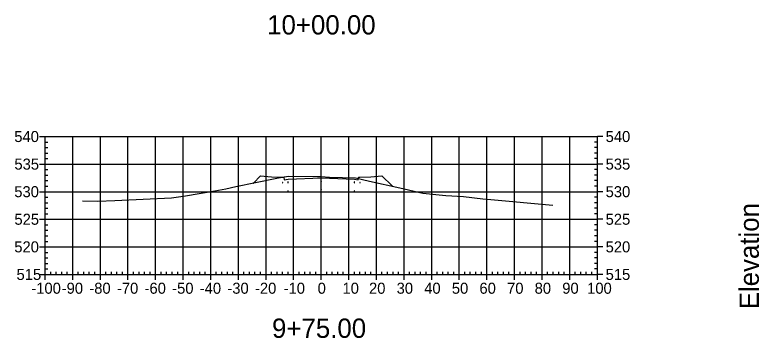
# Model space of a CAD drawing. Extents: x 708103 to 717568, y 374476 to 378707.
# Drawn here: x 716520.5 to 716790.1, y 377195 to 377312.2 of the extents above; entities that cross this region are included whole.
import ezdxf

# ---------------------------------------------------------------- set-up
doc = ezdxf.new("R2010")
doc.units = 0
for name, color, linetype in [('1', 7, 'Continuous'), ('14', 7, 'Continuous'), ('22', 7, 'Continuous'), ('57', 7, 'Continuous'), ('60', 7, 'Continuous'), ('Existing', 7, 'Continuous')]:
    doc.layers.add(name, color=color, linetype=linetype)

msp = doc.modelspace()

# ---------------------------------------------------------------- linework, layer by layer
for points in [[(716617.45, 377251.25), (716617.55, 377251.25), (716617.55, 377251.35), (716617.45, 377251.35)], [(716619.45, 377251.58), (716619.55, 377251.58), (716619.55, 377251.68), (716619.45, 377251.68)], [(716619.45, 377251.25), (716619.55, 377251.25), (716619.55, 377251.35), (716619.45, 377251.35)], [(716631.45, 377251.73), (716631.55, 377251.73), (716631.55, 377251.83), (716631.45, 377251.83)], [(716643.45, 377251.58), (716643.55, 377251.58), (716643.55, 377251.68), (716643.45, 377251.68)], [(716643.45, 377251.25), (716643.55, 377251.25), (716643.55, 377251.35), (716643.45, 377251.35)], [(716645.45, 377251.25), (716645.55, 377251.25), (716645.55, 377251.35), (716645.45, 377251.35)], [(716619.45, 377248.25), (716619.55, 377248.25), (716619.55, 377248.35), (716619.45, 377248.35)], [(716631.45, 377248.73), (716631.55, 377248.73), (716631.55, 377248.83), (716631.45, 377248.83)], [(716643.45, 377248.25), (716643.55, 377248.25), (716643.55, 377248.35), (716643.45, 377248.35)]]:
    msp.add_lwpolyline(points, close=True)
at = {"layer": '14'}
for points in [[(716606.92, 377251.2), (716606.92, 377251.25), (716606.92, 377251.2), (716606.87, 377251.2), (716606.92, 377251.2), (716606.92, 377251.15), (716606.92, 377251.2), (716606.97, 377251.2)], [(716657.14, 377250.14), (716657.14, 377250.19), (716657.14, 377250.14), (716657.09, 377250.14), (716657.14, 377250.14), (716657.14, 377250.09), (716657.14, 377250.14), (716657.19, 377250.14)]]:
    msp.add_lwpolyline(points, dxfattribs=at)
at = {"layer": '22'}
msp.add_lwpolyline([(716606.92, 377251.2), (716609.5, 377253.78), (716613.5, 377253.46), (716617.5, 377253.3), (716618, 377253.3), (716618.08, 377252.38), (716619.5, 377252.63), (716631.5, 377253.11), (716643.5, 377252.63), (716644.91, 377252.38), (716645, 377253.3), (716645.5, 377253.3), (716649.5, 377253.46), (716653.5, 377253.78), (716657.14, 377250.14)], dxfattribs=at)
at = {"layer": '57'}
for p, q in [((716529.5, 377268.07), (716531.5, 377268.07)), ((716531.5, 377268.07), (716731.5, 377268.07)), ((716531.5, 377218.07), (716531.5, 377268.07)), ((716531.5, 377218.07), (716531.5, 377268.07)), ((716541.5, 377218.07), (716541.5, 377268.07)), ((716551.5, 377218.07), (716551.5, 377268.07)), ((716561.5, 377218.07), (716561.5, 377268.07)), ((716571.5, 377218.07), (716571.5, 377268.07)), ((716581.5, 377218.07), (716581.5, 377268.07)), ((716591.5, 377218.07), (716591.5, 377268.07)), ((716601.5, 377218.07), (716601.5, 377268.07)), ((716611.5, 377218.07), (716611.5, 377268.07)), ((716621.5, 377218.07), (716621.5, 377268.07)), ((716631.5, 377218.07), (716631.5, 377268.07)), ((716641.5, 377218.07), (716641.5, 377268.07)), ((716651.5, 377218.07), (716651.5, 377268.07)), ((716661.5, 377218.07), (716661.5, 377268.07)), ((716671.5, 377218.07), (716671.5, 377268.07)), ((716681.5, 377218.07), (716681.5, 377268.07)), ((716691.5, 377218.07), (716691.5, 377268.07)), ((716701.5, 377218.07), (716701.5, 377268.07)), ((716711.5, 377218.07), (716711.5, 377268.07)), ((716721.5, 377218.07), (716721.5, 377268.07)), ((716731.5, 377218.07), (716731.5, 377268.07)), ((716731.5, 377218.07), (716731.5, 377268.07)), ((716733.5, 377268.07), (716731.5, 377268.07)), ((716531.5, 377266.07), (716532.5, 377266.07)), ((716731.5, 377266.07), (716730.5, 377266.07)), ((716531.5, 377264.07), (716532.5, 377264.07)), ((716531.5, 377262.07), (716532.5, 377262.07)), ((716731.5, 377264.07), (716730.5, 377264.07)), ((716731.5, 377262.07), (716730.5, 377262.07)), ((716531.5, 377260.07), (716532.5, 377260.07)), ((716731.5, 377260.07), (716730.5, 377260.07)), ((716529.5, 377258.07), (716531.5, 377258.07)), ((716531.5, 377258.07), (716731.5, 377258.07)), ((716733.5, 377258.07), (716731.5, 377258.07)), ((716531.5, 377256.07), (716532.5, 377256.07)), ((716531.5, 377254.07), (716532.5, 377254.07)), ((716731.5, 377256.07), (716730.5, 377256.07)), ((716731.5, 377254.07), (716730.5, 377254.07)), ((716531.5, 377252.07), (716532.5, 377252.07)), ((716731.5, 377252.07), (716730.5, 377252.07)), ((716531.5, 377250.07), (716532.5, 377250.07)), ((716731.5, 377250.07), (716730.5, 377250.07)), ((716529.5, 377248.07), (716531.5, 377248.07)), ((716531.5, 377248.07), (716731.5, 377248.07)), ((716531.5, 377246.07), (716532.5, 377246.07)), ((716731.5, 377246.07), (716730.5, 377246.07)), ((716733.5, 377248.07), (716731.5, 377248.07)), ((716531.5, 377244.07), (716532.5, 377244.07)), ((716731.5, 377244.07), (716730.5, 377244.07)), ((716531.5, 377242.07), (716532.5, 377242.07)), ((716531.5, 377240.07), (716532.5, 377240.07)), ((716731.5, 377242.07), (716730.5, 377242.07)), ((716731.5, 377240.07), (716730.5, 377240.07)), ((716529.5, 377238.07), (716531.5, 377238.07)), ((716531.5, 377238.07), (716731.5, 377238.07)), ((716733.5, 377238.07), (716731.5, 377238.07)), ((716531.5, 377236.07), (716532.5, 377236.07)), ((716731.5, 377236.07), (716730.5, 377236.07)), ((716531.5, 377234.07), (716532.5, 377234.07)), ((716531.5, 377232.07), (716532.5, 377232.07)), ((716731.5, 377234.07), (716730.5, 377234.07)), ((716731.5, 377232.07), (716730.5, 377232.07)), ((716531.5, 377230.07), (716532.5, 377230.07)), ((716731.5, 377230.07), (716730.5, 377230.07)), ((716529.5, 377228.07), (716531.5, 377228.07)), ((716531.5, 377228.07), (716731.5, 377228.07)), ((716733.5, 377228.07), (716731.5, 377228.07)), ((716531.5, 377226.07), (716532.5, 377226.07)), ((716531.5, 377224.07), (716532.5, 377224.07)), ((716731.5, 377226.07), (716730.5, 377226.07)), ((716731.5, 377224.07), (716730.5, 377224.07)), ((716531.5, 377222.07), (716532.5, 377222.07)), ((716731.5, 377222.07), (716730.5, 377222.07)), ((716531.5, 377220.07), (716532.5, 377220.07)), ((716533.5, 377218.07), (716533.5, 377219.07)), ((716535.5, 377218.07), (716535.5, 377219.07)), ((716537.5, 377218.07), (716537.5, 377219.07)), ((716539.5, 377218.07), (716539.5, 377219.07)), ((716543.5, 377218.07), (716543.5, 377219.07)), ((716545.5, 377218.07), (716545.5, 377219.07)), ((716547.5, 377218.07), (716547.5, 377219.07)), ((716549.5, 377218.07), (716549.5, 377219.07)), ((716553.5, 377218.07), (716553.5, 377219.07)), ((716555.5, 377218.07), (716555.5, 377219.07)), ((716557.5, 377218.07), (716557.5, 377219.07)), ((716559.5, 377218.07), (716559.5, 377219.07)), ((716563.5, 377218.07), (716563.5, 377219.07)), ((716565.5, 377218.07), (716565.5, 377219.07)), ((716567.5, 377218.07), (716567.5, 377219.07)), ((716569.5, 377218.07), (716569.5, 377219.07)), ((716573.5, 377218.07), (716573.5, 377219.07)), ((716575.5, 377218.07), (716575.5, 377219.07)), ((716577.5, 377218.07), (716577.5, 377219.07)), ((716579.5, 377218.07), (716579.5, 377219.07)), ((716583.5, 377218.07), (716583.5, 377219.07)), ((716585.5, 377218.07), (716585.5, 377219.07)), ((716587.5, 377218.07), (716587.5, 377219.07)), ((716589.5, 377218.07), (716589.5, 377219.07)), ((716593.5, 377218.07), (716593.5, 377219.07)), ((716595.5, 377218.07), (716595.5, 377219.07)), ((716597.5, 377218.07), (716597.5, 377219.07)), ((716599.5, 377218.07), (716599.5, 377219.07)), ((716603.5, 377218.07), (716603.5, 377219.07)), ((716605.5, 377218.07), (716605.5, 377219.07)), ((716607.5, 377218.07), (716607.5, 377219.07)), ((716609.5, 377218.07), (716609.5, 377219.07)), ((716613.5, 377218.07), (716613.5, 377219.07)), ((716615.5, 377218.07), (716615.5, 377219.07)), ((716617.5, 377218.07), (716617.5, 377219.07)), ((716619.5, 377218.07), (716619.5, 377219.07)), ((716623.5, 377218.07), (716623.5, 377219.07)), ((716625.5, 377218.07), (716625.5, 377219.07)), ((716627.5, 377218.07), (716627.5, 377219.07)), ((716629.5, 377218.07), (716629.5, 377219.07)), ((716633.5, 377218.07), (716633.5, 377219.07)), ((716635.5, 377218.07), (716635.5, 377219.07)), ((716637.5, 377218.07), (716637.5, 377219.07)), ((716639.5, 377218.07), (716639.5, 377219.07)), ((716643.5, 377218.07), (716643.5, 377219.07)), ((716645.5, 377218.07), (716645.5, 377219.07)), ((716647.5, 377218.07), (716647.5, 377219.07)), ((716649.5, 377218.07), (716649.5, 377219.07)), ((716653.5, 377218.07), (716653.5, 377219.07)), ((716655.5, 377218.07), (716655.5, 377219.07)), ((716657.5, 377218.07), (716657.5, 377219.07)), ((716659.5, 377218.07), (716659.5, 377219.07)), ((716663.5, 377218.07), (716663.5, 377219.07)), ((716665.5, 377218.07), (716665.5, 377219.07)), ((716667.5, 377218.07), (716667.5, 377219.07)), ((716669.5, 377218.07), (716669.5, 377219.07)), ((716673.5, 377218.07), (716673.5, 377219.07)), ((716675.5, 377218.07), (716675.5, 377219.07)), ((716677.5, 377218.07), (716677.5, 377219.07)), ((716679.5, 377218.07), (716679.5, 377219.07)), ((716683.5, 377218.07), (716683.5, 377219.07)), ((716685.5, 377218.07), (716685.5, 377219.07)), ((716687.5, 377218.07), (716687.5, 377219.07)), ((716689.5, 377218.07), (716689.5, 377219.07)), ((716693.5, 377218.07), (716693.5, 377219.07)), ((716695.5, 377218.07), (716695.5, 377219.07)), ((716697.5, 377218.07), (716697.5, 377219.07)), ((716699.5, 377218.07), (716699.5, 377219.07)), ((716703.5, 377218.07), (716703.5, 377219.07)), ((716705.5, 377218.07), (716705.5, 377219.07)), ((716707.5, 377218.07), (716707.5, 377219.07)), ((716709.5, 377218.07), (716709.5, 377219.07)), ((716713.5, 377218.07), (716713.5, 377219.07)), ((716715.5, 377218.07), (716715.5, 377219.07)), ((716717.5, 377218.07), (716717.5, 377219.07)), ((716719.5, 377218.07), (716719.5, 377219.07)), ((716723.5, 377218.07), (716723.5, 377219.07)), ((716725.5, 377218.07), (716725.5, 377219.07)), ((716727.5, 377218.07), (716727.5, 377219.07)), ((716729.5, 377218.07), (716729.5, 377219.07)), ((716731.5, 377220.07), (716730.5, 377220.07)), ((716529.5, 377218.07), (716531.5, 377218.07)), ((716531.5, 377218.07), (716731.5, 377218.07)), ((716531.5, 377218.07), (716731.5, 377218.07)), ((716531.5, 377216.07), (716531.5, 377218.07)), ((716541.5, 377216.07), (716541.5, 377218.07)), ((716551.5, 377216.07), (716551.5, 377218.07)), ((716561.5, 377216.07), (716561.5, 377218.07)), ((716571.5, 377216.07), (716571.5, 377218.07)), ((716581.5, 377216.07), (716581.5, 377218.07)), ((716591.5, 377216.07), (716591.5, 377218.07)), ((716601.5, 377216.07), (716601.5, 377218.07)), ((716611.5, 377216.07), (716611.5, 377218.07)), ((716621.5, 377216.07), (716621.5, 377218.07)), ((716631.5, 377216.07), (716631.5, 377218.07)), ((716641.5, 377216.07), (716641.5, 377218.07)), ((716651.5, 377216.07), (716651.5, 377218.07)), ((716661.5, 377216.07), (716661.5, 377218.07)), ((716671.5, 377216.07), (716671.5, 377218.07)), ((716681.5, 377216.07), (716681.5, 377218.07)), ((716691.5, 377216.07), (716691.5, 377218.07)), ((716701.5, 377216.07), (716701.5, 377218.07)), ((716711.5, 377216.07), (716711.5, 377218.07)), ((716721.5, 377216.07), (716721.5, 377218.07)), ((716731.5, 377216.07), (716731.5, 377218.07)), ((716733.5, 377218.07), (716731.5, 377218.07))]:
    msp.add_line(p, q, dxfattribs=at)
at = {"layer": 'Existing'}
msp.add_lwpolyline([(716545.04, 377244.77), (716550.53, 377244.6), (716556.7, 377244.88), (716577.32, 377245.89), (716582.35, 377246.57), (716592.93, 377248.43), (716596.93, 377249.15), (716600.57, 377249.9), (716614.77, 377252.82), (716617.32, 377253.38), (716619.6, 377253.68), (716630.11, 377253.54), (716631.53, 377253.55), (716634.51, 377253.37), (716643.95, 377253.06), (716649.01, 377251.93), (716659.91, 377249.52), (716668.27, 377247.59), (716676.66, 377246.63), (716683.04, 377246.35), (716690.03, 377245.44), (716692.9, 377245.18), (716715.35, 377243.14)], dxfattribs=at)

# ---------------------------------------------------------------- texts
at = {"layer": '1'}
for s, p in [('10+00.00', (716611.9, 377305.07)), ('9+75.00', (716613.67, 377195.07))]:
    msp.add_text(s, height=7, dxfattribs=at).set_placement(p)
at = {"layer": '14'}
for p in [(716613.46, 377253.41), (716613.46, 377252.74), (716617.46, 377252.58), (716645.46, 377252.58), (716649.46, 377253.41), (716649.46, 377252.74)]:
    msp.add_text('+', height=0.1, dxfattribs=at).set_placement(p)
at = {"layer": '57'}
for s, p in [('540', (716520.32, 377266.07)), ('540', (716734.5, 377266.07)), ('535', (716520.37, 377256.07)), ('535', (716734.5, 377256.07)), ('530', (716520.32, 377246.07)), ('530', (716734.5, 377246.07)), ('525', (716520.37, 377236.07)), ('525', (716734.5, 377236.07)), ('520', (716520.32, 377226.07)), ('520', (716734.5, 377226.07)), ('515', (716521.14, 377216.07)), ('515', (716734.5, 377216.07)), ('-100', (716526.49, 377211.07)), ('-90', (716537.5, 377211.07)), ('-80', (716547.5, 377211.07)), ('-70', (716557.5, 377211.07)), ('-60', (716567.5, 377211.07)), ('-50', (716577.5, 377211.07)), ('-40', (716587.5, 377211.07)), ('-30', (716597.5, 377211.07)), ('-20', (716607.5, 377211.07)), ('-10', (716617.88, 377211.07)), ('0', (716630.2, 377211.07)), ('10', (716639.19, 377211.07)), ('20', (716648.8, 377211.07)), ('30', (716658.8, 377211.07)), ('40', (716668.8, 377211.07)), ('50', (716678.8, 377211.07)), ('60', (716688.8, 377211.07)), ('70', (716698.8, 377211.07)), ('80', (716708.8, 377211.07)), ('90', (716718.8, 377211.07)), ('100', (716727.8, 377211.07))]:
    msp.add_text(s, height=4, dxfattribs=at).set_placement(p)
at = {"layer": '60'}
msp.add_text('Elevation', height=7, rotation=90, dxfattribs=at).set_placement((716790, 377205.44))

doc.saveas('drawing.dxf')
